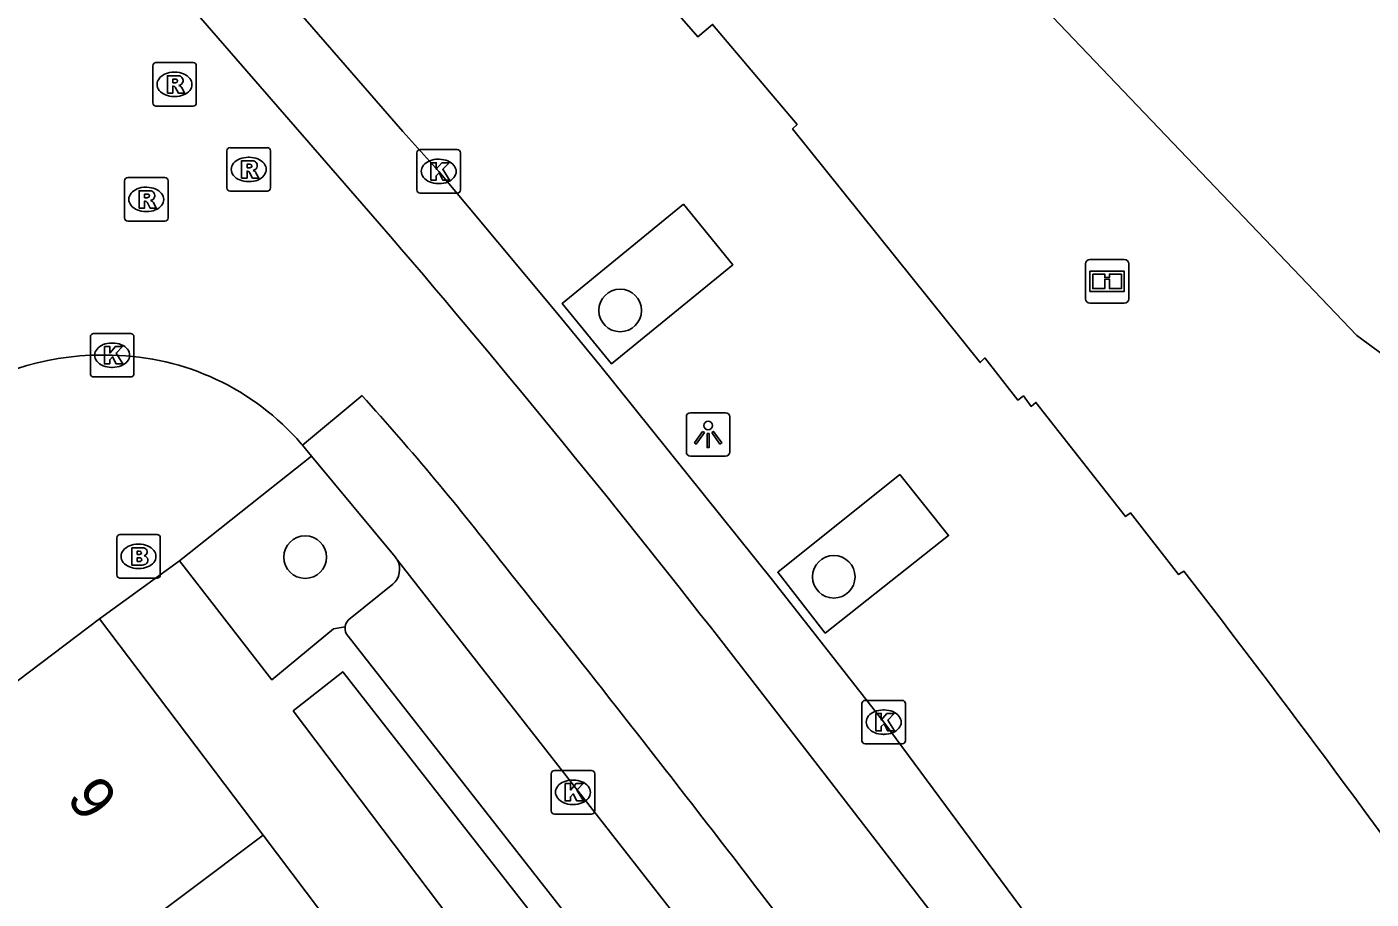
# Model space of a CAD drawing. Extents: x 159718 to 160783, y 383290 to 384030.
# Drawn here: x 160527.17 to 160558.03, y 383509.7 to 383529.73 of the extents above; entities that cross this region are included whole.
import ezdxf

# ---------------------------------------------------------------- set-up
doc = ezdxf.new("R2010")
doc.units = 0
for name, color, linetype in [('IMGEO_Boom', 7, 'Continuous'), ('IMGEO_Brandkraan', 7, 'Continuous'), ('IMGEO_Informatiebord', 7, 'Continuous'), ('IMGEO_Kolk', 7, 'Continuous'), ('IMGEO_Lichtpunt', 7, 'Continuous'), ('IMGEO_Pand', 7, 'Continuous'), ('IMGEO_Pand_nummerreeks', 7, 'Continuous'), ('IMGEO_Parkeervlak_open', 7, 'Continuous'), ('IMGEO_Rijbaan_lokaal_gesloten', 7, 'Continuous'), ('IMGEO_Rijbaan_lokaal_open', 7, 'Continuous'), ('IMGEO_Rioolput', 7, 'Continuous'), ('IMGEO_Voetpad_open', 7, 'Continuous')]:
    doc.layers.add(name, color=color, linetype=linetype)

msp = doc.modelspace()

# ---------------------------------------------------------------- linework, layer by layer
at = {"layer": 'IMGEO_Boom'}
for centre in [(160540.789, 383523.222), (160533.556, 383517.555), (160545.693, 383517.104)]:
    msp.add_circle(centre, 0.489, dxfattribs=at)
at = {"layer": 'IMGEO_Brandkraan'}
for p, q in [((160529.228, 383517.146), (160529.228, 383517.998)), ((160529.303, 383518.072), (160530.155, 383518.072)), ((160529.716, 383517.852), (160529.741, 383517.852)), ((160530.229, 383517.998), (160530.229, 383517.146)), ((160529.739, 383517.292), (160529.714, 383517.292)), ((160530.155, 383517.072), (160529.303, 383517.072))]:
    msp.add_line(p, q, dxfattribs=at)
for points in [[(160529.228, 383517.146), (160529.228, 383517.998)], [(160529.303, 383518.072), (160530.155, 383518.072)], [(160530.229, 383517.998), (160530.229, 383517.146)], [(160529.576, 383517.772), (160529.576, 383517.372), (160529.789, 383517.372)], [(160529.807, 383517.772), (160529.576, 383517.772)], [(160529.755, 383517.691), (160529.701, 383517.691), (160529.701, 383517.615)], [(160529.701, 383517.615), (160529.754, 383517.615)], [(160529.763, 383517.539), (160529.701, 383517.539), (160529.701, 383517.458)], [(160529.701, 383517.458), (160529.763, 383517.458)], [(160530.155, 383517.072), (160529.303, 383517.072)]]:
    msp.add_lwpolyline(points, dxfattribs=at)
for centre, radius, start, end in [((160529.305, 383517.996), 0.0765, 91.552, 178.448), ((160529.305, 383517.996), 0.0765, 91.552, 178.448), ((160530.153, 383517.996), 0.0765, 1.552, 88.448), ((160530.153, 383517.996), 0.0765, 1.552, 88.448), ((160529.756, 383517.653), 0.0379, 267.8285, 90.9355), ((160529.764, 383517.498), 0.0404, 269.8759, 90.5077), ((160529.811, 383517.627), 0.145, 59.4692, 91.5367), ((160529.836, 383517.674), 0.0922, 285.5137, 58.1501), ((160529.841, 383517.482), 0.105, 301.3115, 78.989), ((160529.795, 383517.623), 0.251, 268.6676, 293.5347), ((160529.305, 383517.148), 0.0765, 181.552, 268.448), ((160529.305, 383517.148), 0.0765, 181.552, 268.448), ((160530.153, 383517.148), 0.0765, 271.552, 358.448), ((160530.153, 383517.148), 0.0765, 271.552, 358.448)]:
    msp.add_arc(centre, radius, start, end, dxfattribs=at)
for centre, major_axis, ratio, start_param, end_param in [((160529.715, 383517.572), (-0.387, 0.002), 0.722429, 4.712389, 7.853982), ((160529.74, 383517.572), (-0.39, 0.002), 0.717154, 1.570796, 4.712389)]:
    msp.add_ellipse(centre, major_axis=major_axis, ratio=ratio, start_param=start_param, end_param=end_param, dxfattribs=at)
at = {"layer": 'IMGEO_Informatiebord'}
for p, q in [((160551.476, 383523.489), (160551.476, 383524.289)), ((160551.476, 383524.289), (160551.476, 383523.489)), ((160551.576, 383524.389), (160552.366, 383524.389)), ((160552.366, 383524.389), (160551.576, 383524.389)), ((160552.466, 383524.289), (160552.466, 383523.489)), ((160552.466, 383523.489), (160552.466, 383524.289)), ((160552.366, 383523.389), (160551.576, 383523.389)), ((160551.576, 383523.389), (160552.366, 383523.389))]:
    msp.add_line(p, q, dxfattribs=at)
for points in [[(160551.577, 383524.121), (160552.365, 383524.121), (160552.365, 383523.657), (160551.577, 383523.657), (160551.577, 383524.121)], [(160551.642, 383524.056), (160551.642, 383523.722), (160551.917, 383523.722), (160551.918, 383523.935), (160552.022, 383523.936), (160552.023, 383523.722), (160552.3, 383523.722), (160552.3, 383524.056), (160552.024, 383524.056), (160552.024, 383523.976), (160551.918, 383523.976), (160551.918, 383524.056), (160551.642, 383524.056)]]:
    msp.add_lwpolyline(points, dxfattribs=at)
for centre, start, end in [((160551.576, 383524.289), 90, 180), ((160551.576, 383524.289), 90, 180), ((160552.366, 383524.289), 0, 90), ((160552.366, 383524.289), 360, 90), ((160551.576, 383523.489), 180, 270), ((160551.576, 383523.489), 180, 270), ((160552.366, 383523.489), 270, 0), ((160552.366, 383523.489), 270, 0)]:
    msp.add_arc(centre, 0.1, start, end, dxfattribs=at)
at = {"layer": 'IMGEO_Kolk'}
for p, q in [((160536.122, 383525.989), (160536.122, 383526.841)), ((160536.197, 383526.915), (160537.049, 383526.915)), ((160537.123, 383526.841), (160537.123, 383525.989)), ((160536.61, 383526.695), (160536.635, 383526.695)), ((160537.049, 383525.915), (160536.197, 383525.915)), ((160536.633, 383526.135), (160536.608, 383526.135)), ((160528.623, 383521.767), (160528.623, 383522.619)), ((160528.698, 383522.693), (160529.55, 383522.693)), ((160529.111, 383522.473), (160529.136, 383522.473)), ((160529.624, 383522.619), (160529.624, 383521.767)), ((160529.134, 383521.913), (160529.109, 383521.913)), ((160529.55, 383521.693), (160528.698, 383521.693)), ((160546.34, 383513.338), (160546.34, 383514.19)), ((160546.415, 383514.264), (160547.267, 383514.264)), ((160547.341, 383514.19), (160547.341, 383513.338)), ((160546.828, 383514.044), (160546.853, 383514.044)), ((160546.851, 383513.484), (160546.826, 383513.484)), ((160547.267, 383513.264), (160546.415, 383513.264)), ((160539.203, 383511.727), (160539.203, 383512.579)), ((160539.278, 383512.653), (160540.13, 383512.653)), ((160540.204, 383512.579), (160540.204, 383511.727)), ((160539.691, 383512.433), (160539.716, 383512.433)), ((160540.13, 383511.653), (160539.278, 383511.653)), ((160539.714, 383511.873), (160539.689, 383511.873))]:
    msp.add_line(p, q, dxfattribs=at)
for points in [[(160536.122, 383525.989), (160536.122, 383526.841)], [(160536.197, 383526.915), (160537.049, 383526.915)], [(160537.123, 383526.841), (160537.123, 383525.989)], [(160536.443, 383526.615), (160536.566, 383526.615), (160536.566, 383526.464), (160536.696, 383526.615), (160536.86, 383526.615), (160536.714, 383526.464), (160536.867, 383526.215), (160536.715, 383526.215), (160536.63, 383526.379), (160536.566, 383526.312), (160536.566, 383526.215), (160536.443, 383526.215), (160536.443, 383526.615)], [(160537.049, 383525.915), (160536.197, 383525.915)], [(160528.623, 383521.767), (160528.623, 383522.619)], [(160528.698, 383522.693), (160529.55, 383522.693)], [(160529.624, 383522.619), (160529.624, 383521.767)], [(160528.944, 383522.393), (160529.067, 383522.393), (160529.067, 383522.242), (160529.197, 383522.393), (160529.361, 383522.393), (160529.215, 383522.242), (160529.368, 383521.993), (160529.216, 383521.993), (160529.131, 383522.157), (160529.067, 383522.09), (160529.067, 383521.993), (160528.944, 383521.993), (160528.944, 383522.393)], [(160529.55, 383521.693), (160528.698, 383521.693)], [(160546.34, 383513.338), (160546.34, 383514.19)], [(160546.415, 383514.264), (160547.267, 383514.264)], [(160547.341, 383514.19), (160547.341, 383513.338)], [(160546.661, 383513.964), (160546.784, 383513.964), (160546.784, 383513.813), (160546.914, 383513.964), (160547.078, 383513.964), (160546.932, 383513.813), (160547.085, 383513.564), (160546.933, 383513.564), (160546.848, 383513.728), (160546.784, 383513.661), (160546.784, 383513.564), (160546.661, 383513.564), (160546.661, 383513.964)], [(160547.267, 383513.264), (160546.415, 383513.264)], [(160539.203, 383511.727), (160539.203, 383512.579)], [(160539.278, 383512.653), (160540.13, 383512.653)], [(160540.204, 383512.579), (160540.204, 383511.727)], [(160539.524, 383512.353), (160539.647, 383512.353), (160539.647, 383512.202), (160539.777, 383512.353), (160539.941, 383512.353), (160539.795, 383512.202), (160539.948, 383511.953), (160539.796, 383511.953), (160539.711, 383512.117), (160539.647, 383512.05), (160539.647, 383511.953), (160539.524, 383511.953), (160539.524, 383512.353)], [(160540.13, 383511.653), (160539.278, 383511.653)]]:
    msp.add_lwpolyline(points, dxfattribs=at)
for centre, start, end in [((160536.199, 383526.839), 91.552, 178.448), ((160536.199, 383526.839), 91.552, 178.448), ((160537.047, 383526.839), 1.552, 88.448), ((160537.047, 383526.839), 1.552, 88.448), ((160536.199, 383525.991), 181.552, 268.448), ((160536.199, 383525.991), 181.552, 268.448), ((160537.047, 383525.991), 271.552, 358.448), ((160537.047, 383525.991), 271.552, 358.448), ((160528.7, 383522.617), 91.552, 178.448), ((160528.7, 383522.617), 91.552, 178.448), ((160529.548, 383522.617), 1.552, 88.448), ((160529.548, 383522.617), 1.552, 88.448), ((160528.7, 383521.769), 181.552, 268.448), ((160528.7, 383521.769), 181.552, 268.448), ((160529.548, 383521.769), 271.552, 358.448), ((160529.548, 383521.769), 271.552, 358.448), ((160546.417, 383514.188), 91.552, 178.448), ((160546.417, 383514.188), 91.552, 178.448), ((160547.265, 383514.188), 1.552, 88.448), ((160547.265, 383514.188), 1.552, 88.448), ((160546.417, 383513.34), 181.552, 268.448), ((160546.417, 383513.34), 181.552, 268.448), ((160547.265, 383513.34), 271.552, 358.448), ((160547.265, 383513.34), 271.552, 358.448), ((160539.28, 383512.577), 91.552, 178.448), ((160539.28, 383512.577), 91.552, 178.448), ((160540.128, 383512.577), 1.552, 88.448), ((160540.128, 383512.577), 1.552, 88.448), ((160539.28, 383511.729), 181.552, 268.448), ((160539.28, 383511.729), 181.552, 268.448), ((160540.128, 383511.729), 271.552, 358.448), ((160540.128, 383511.729), 271.552, 358.448)]:
    msp.add_arc(centre, 0.0765, start, end, dxfattribs=at)
for centre, major_axis, ratio, start_param, end_param in [((160536.609, 383526.415), (-0.387, 0.002), 0.722429, 4.712389, 7.853982), ((160536.634, 383526.415), (-0.39, 0.002), 0.717154, 1.570796, 4.712389), ((160529.11, 383522.193), (-0.387, 0.002), 0.722429, 4.712389, 7.853982), ((160529.135, 383522.193), (-0.39, 0.002), 0.717154, 1.570796, 4.712389), ((160546.827, 383513.764), (-0.387, 0.002), 0.722429, 4.712389, 7.853982), ((160546.852, 383513.764), (-0.39, 0.002), 0.717154, 1.570796, 4.712389), ((160539.69, 383512.153), (-0.387, 0.002), 0.722429, 4.712389, 7.853982), ((160539.715, 383512.153), (-0.39, 0.002), 0.717154, 1.570796, 4.712389)]:
    msp.add_ellipse(centre, major_axis=major_axis, ratio=ratio, start_param=start_param, end_param=end_param, dxfattribs=at)
at = {"layer": 'IMGEO_Lichtpunt'}
for p, q in [((160542.309, 383520.778), (160542.309, 383519.971)), ((160542.309, 383520.778), (160542.309, 383519.971)), ((160543.211, 383520.873), (160542.403, 383520.873)), ((160543.211, 383520.873), (160542.403, 383520.873)), ((160543.305, 383519.971), (160543.305, 383520.778)), ((160543.305, 383519.971), (160543.305, 383520.778)), ((160542.403, 383519.877), (160543.211, 383519.877)), ((160542.403, 383519.877), (160543.211, 383519.877))]:
    msp.add_line(p, q, dxfattribs=at)
for points in [[(160542.683, 383520.442), (160542.722, 383520.414), (160542.534, 383520.152), (160542.496, 383520.179), (160542.683, 383520.442)], [(160542.785, 383520.394), (160542.832, 383520.394), (160542.832, 383520.072), (160542.785, 383520.072), (160542.785, 383520.394)], [(160542.895, 383520.414), (160542.933, 383520.441), (160543.12, 383520.179), (160543.081, 383520.151), (160542.895, 383520.414)]]:
    msp.add_lwpolyline(points, dxfattribs=at)
msp.add_circle((160542.808, 383520.576), 0.0994, dxfattribs=at)
for centre, start, end in [((160542.403, 383520.778), 90, 180), ((160542.403, 383520.778), 90, 180), ((160543.211, 383520.778), 0, 90), ((160543.211, 383520.778), 0, 90), ((160542.403, 383519.971), 180, 270), ((160542.403, 383519.971), 180, 270), ((160543.211, 383519.971), 270, 0), ((160543.211, 383519.971), 270, 360)]:
    msp.add_arc(centre, 0.0946, start, end, dxfattribs=at)
at = {"layer": 'IMGEO_Pand'}
for points in [[(160528.836, 383516.141), (160521.892, 383510.886)], [(160532.589, 383511.169), (160528.836, 383516.141)], [(160520.224, 383501.882), (160532.589, 383511.169)], [(160536.235, 383506.34), (160532.589, 383511.169)]]:
    msp.add_lwpolyline(points, dxfattribs=at)
at = {"layer": 'IMGEO_Parkeervlak_open'}
msp.add_lwpolyline([(160535.57, 383516.934), (160534.589, 383516.144)], dxfattribs=at)
for centre, radius, start, end in [((160535.27, 383517.275), 0.455, 311.3566, 27.4669), ((160534.742, 383515.921), 0.271, 124.4712, 173.7751)]:
    msp.add_arc(centre, radius, start, end, dxfattribs=at)
at = {"layer": 'IMGEO_Rijbaan_lokaal_gesloten'}
for points in [[(160482.526, 383588.525), (160483.151, 383587.858), (160493.318, 383576.241), (160507.09, 383560.37), (160517.403, 383548.451), (160520.715, 383544.684), (160521.52, 383543.759), (160535.801, 383527.329), (160536.623, 383526.415), (160539.338, 383523.165), (160540.32, 383521.963), (160544.286, 383517.022), (160545.265, 383515.781), (160546.841, 383513.764), (160554.904, 383502.868), (160555.82, 383501.543), (160555.982, 383501.307), (160556.128, 383501.1)], [(160535.265, 383525.211), (160519.878, 383542.924), (160497.457, 383568.737)], [(160533.492, 383520.126), (160534.861, 383521.268)], [(160533.701, 383519.875), (160533.492, 383520.126)], [(160533.701, 383519.875), (160535.625, 383517.558), (160535.655, 383517.517), (160535.673, 383517.485)], [(160535.673, 383517.485), (160543.509, 383507.473)], [(160548.14, 383509.131), (160545.624, 383512.385), (160543.098, 383515.647)]]:
    msp.add_lwpolyline(points, dxfattribs=at)
for centre, radius, start, end in [((160338.893, 383356.391), 258.964, 37.95007, 40.68548), ((160484.478, 383475.841), 67.838, 37.72141, 42.03901), ((160177.503, 383228.961), 461.762, 36.59537, 38.64783)]:
    msp.add_arc(centre, radius, start, end, dxfattribs=at)
at = {"layer": 'IMGEO_Rijbaan_lokaal_open'}
for points in [[(160511.866, 383562.752), (160515.816, 383566.523), (160516.087, 383566.239), (160557.707, 383522.642), (160573.646, 383510.923)], [(160533.492, 383520.126), (160533.465, 383520.159)]]:
    msp.add_lwpolyline(points, dxfattribs=at)
for centre, radius, start, end in [((160528.885, 383515.966), 6.231, 87.8013, 124.2831), ((160529.016, 383516.312), 5.882, 40.8449, 88.9436)]:
    msp.add_arc(centre, radius, start, end, dxfattribs=at)
at = {"layer": 'IMGEO_Rioolput'}
for p, q in [((160530.055, 383527.988), (160530.055, 383528.84)), ((160530.13, 383528.914), (160530.982, 383528.914)), ((160530.543, 383528.694), (160530.568, 383528.694)), ((160531.056, 383528.84), (160531.056, 383527.988)), ((160530.566, 383528.134), (160530.541, 383528.134)), ((160530.982, 383527.914), (160530.13, 383527.914)), ((160531.76, 383526.034), (160531.76, 383526.886)), ((160531.835, 383526.96), (160532.687, 383526.96)), ((160532.761, 383526.886), (160532.761, 383526.034)), ((160532.248, 383526.74), (160532.273, 383526.74)), ((160529.406, 383525.346), (160529.406, 383526.198)), ((160529.481, 383526.272), (160530.333, 383526.272)), ((160530.407, 383526.198), (160530.407, 383525.346)), ((160532.271, 383526.18), (160532.246, 383526.18)), ((160529.894, 383526.052), (160529.919, 383526.052)), ((160532.687, 383525.96), (160531.835, 383525.96)), ((160530.333, 383525.272), (160529.481, 383525.272)), ((160529.917, 383525.492), (160529.892, 383525.492))]:
    msp.add_line(p, q, dxfattribs=at)
for points in [[(160530.055, 383527.988), (160530.055, 383528.84)], [(160530.13, 383528.914), (160530.982, 383528.914)], [(160530.644, 383528.612), (160530.392, 383528.614), (160530.392, 383528.214)], [(160531.056, 383528.84), (160531.056, 383527.988)], [(160530.392, 383528.214), (160530.516, 383528.214), (160530.516, 383528.376), (160530.527, 383528.376)], [(160530.57, 383528.533), (160530.516, 383528.533), (160530.516, 383528.452)], [(160530.516, 383528.452), (160530.568, 383528.452)], [(160530.574, 383528.347), (160530.645, 383528.214), (160530.785, 383528.214), (160530.72, 383528.34)], [(160530.982, 383527.914), (160530.13, 383527.914)], [(160531.76, 383526.034), (160531.76, 383526.886)], [(160531.835, 383526.96), (160532.687, 383526.96)], [(160532.761, 383526.886), (160532.761, 383526.034)], [(160532.349, 383526.658), (160532.097, 383526.66), (160532.097, 383526.26)], [(160532.275, 383526.579), (160532.221, 383526.579), (160532.221, 383526.498)], [(160532.221, 383526.498), (160532.273, 383526.498)], [(160529.406, 383525.346), (160529.406, 383526.198)], [(160529.481, 383526.272), (160530.333, 383526.272)], [(160530.407, 383526.198), (160530.407, 383525.346)], [(160532.097, 383526.26), (160532.221, 383526.26), (160532.221, 383526.422), (160532.232, 383526.422)], [(160532.279, 383526.393), (160532.35, 383526.26), (160532.49, 383526.26), (160532.425, 383526.386)], [(160529.995, 383525.97), (160529.743, 383525.972), (160529.743, 383525.572)], [(160529.921, 383525.891), (160529.867, 383525.891), (160529.867, 383525.81)], [(160532.687, 383525.96), (160531.835, 383525.96)], [(160529.743, 383525.572), (160529.867, 383525.572), (160529.867, 383525.734), (160529.878, 383525.734)], [(160529.867, 383525.81), (160529.919, 383525.81)], [(160529.925, 383525.705), (160529.996, 383525.572), (160530.136, 383525.572), (160530.071, 383525.698)], [(160530.333, 383525.272), (160529.481, 383525.272)]]:
    msp.add_lwpolyline(points, dxfattribs=at)
for centre, radius, start, end in [((160530.132, 383528.838), 0.0765, 91.552, 178.448), ((160530.132, 383528.838), 0.0765, 91.552, 178.448), ((160530.643, 383528.502), 0.109, 350.3612, 89.416), ((160530.98, 383528.838), 0.0765, 1.552, 88.448), ((160530.98, 383528.838), 0.0765, 1.552, 88.448), ((160530.526, 383528.323), 0.0533, 26.0293, 88.6989), ((160530.552, 383528.641), 0.19, 274.7715, 282.9687), ((160530.576, 383528.437), 0.0964, 77.0061, 93.1865), ((160530.59, 383528.494), 0.0378, 276.6634, 79.6772), ((160530.641, 383528.502), 0.112, 277.5842, 350.9817), ((160530.625, 383528.287), 0.108, 29.5134, 73.7905), ((160530.132, 383527.99), 0.0765, 181.552, 268.448), ((160530.132, 383527.99), 0.0765, 181.552, 268.448), ((160530.98, 383527.99), 0.0765, 271.552, 358.448), ((160530.98, 383527.99), 0.0765, 271.552, 358.448), ((160531.837, 383526.884), 0.0765, 91.552, 178.448), ((160531.837, 383526.884), 0.0765, 91.552, 178.448), ((160532.685, 383526.884), 0.0765, 1.552, 88.448), ((160532.685, 383526.884), 0.0765, 1.552, 88.448), ((160532.257, 383526.687), 0.19, 274.7715, 282.9687), ((160532.281, 383526.483), 0.0964, 77.0061, 93.1865), ((160532.295, 383526.54), 0.0378, 276.6634, 79.6772), ((160532.348, 383526.548), 0.109, 350.3612, 89.416), ((160532.346, 383526.548), 0.112, 277.5842, 350.9817), ((160529.483, 383526.196), 0.0765, 91.552, 178.448), ((160529.483, 383526.196), 0.0765, 91.552, 178.448), ((160530.331, 383526.196), 0.0765, 1.552, 88.448), ((160530.331, 383526.196), 0.0765, 1.552, 88.448), ((160532.231, 383526.369), 0.0533, 26.0293, 88.6989), ((160532.33, 383526.333), 0.108, 29.5134, 73.7905), ((160529.927, 383525.795), 0.0964, 77.0061, 93.1865), ((160529.941, 383525.852), 0.0378, 276.6634, 79.6772), ((160529.994, 383525.86), 0.109, 350.3612, 89.416), ((160529.992, 383525.86), 0.112, 277.5842, 350.9817), ((160531.837, 383526.036), 0.0765, 181.552, 268.448), ((160531.837, 383526.036), 0.0765, 181.552, 268.448), ((160532.685, 383526.036), 0.0765, 271.552, 358.448), ((160532.685, 383526.036), 0.0765, 271.552, 358.448), ((160529.877, 383525.681), 0.0533, 26.0293, 88.6989), ((160529.903, 383525.999), 0.19, 274.7715, 282.9687), ((160529.976, 383525.645), 0.108, 29.5134, 73.7905), ((160529.483, 383525.348), 0.0765, 181.552, 268.448), ((160529.483, 383525.348), 0.0765, 181.552, 268.448), ((160530.331, 383525.348), 0.0765, 271.552, 358.448), ((160530.331, 383525.348), 0.0765, 271.552, 358.448)]:
    msp.add_arc(centre, radius, start, end, dxfattribs=at)
for centre, major_axis, ratio, start_param, end_param in [((160530.542, 383528.414), (-0.387, 0.002), 0.722429, 4.712389, 7.853982), ((160530.567, 383528.414), (-0.39, 0.002), 0.717154, 1.570796, 4.712389), ((160532.247, 383526.46), (-0.387, 0.002), 0.722429, 4.712389, 7.853982), ((160532.272, 383526.46), (-0.39, 0.002), 0.717154, 1.570796, 4.712389), ((160529.893, 383525.772), (-0.387, 0.002), 0.722429, 4.712389, 7.853982), ((160529.918, 383525.772), (-0.39, 0.002), 0.717154, 1.570796, 4.712389)]:
    msp.add_ellipse(centre, major_axis=major_axis, ratio=ratio, start_param=start_param, end_param=end_param, dxfattribs=at)
at = {"layer": 'IMGEO_Voetpad_open'}
for points in [[(160538.911, 383533.701), (160542.576, 383529.504), (160542.912, 383529.792), (160544.85, 383527.489), (160544.748, 383527.395), (160549.057, 383522.022), (160549.159, 383522.131), (160549.92, 383521.164), (160550.048, 383521.258), (160550.229, 383521.017), (160550.336, 383521.109), (160552.396, 383518.485), (160552.504, 383518.571), (160553.613, 383517.153), (160553.733, 383517.232), (160554.594, 383516.112)], [(160542.247, 383525.663), (160543.373, 383524.272), (160540.589, 383521.998), (160539.46, 383523.382), (160542.247, 383525.663)], [(160530.673, 383517.466), (160532.785, 383519.15), (160533.701, 383519.875)], [(160547.209, 383519.454), (160548.33, 383518.049), (160545.5, 383515.81), (160544.408, 383517.207), (160547.209, 383519.454)], [(160530.673, 383517.466), (160528.836, 383516.141)], [(160534.473, 383515.95), (160534.205, 383515.906), (160532.794, 383514.735), (160530.673, 383517.466)], [(160541.568, 383506.768), (160534.544, 383515.738)], [(160533.277, 383514.021), (160534.419, 383514.92), (160540.75, 383506.82), (160539.483, 383505.815), (160533.277, 383514.021)]]:
    msp.add_lwpolyline(points, dxfattribs=at)
for centre, radius, start, end in [((160337.54, 383350.046), 273.295, 34.97426, 37.41931), ((160534.735, 383515.92), 0.264, 173.4753, 223.5566)]:
    msp.add_arc(centre, radius, start, end, dxfattribs=at)

# ---------------------------------------------------------------- texts
at = {"layer": 'IMGEO_Pand_nummerreeks'}
msp.add_text('9', height=1, rotation=306.9097, dxfattribs=at).set_placement((160528.052, 383512.014))

doc.saveas('drawing.dxf')
